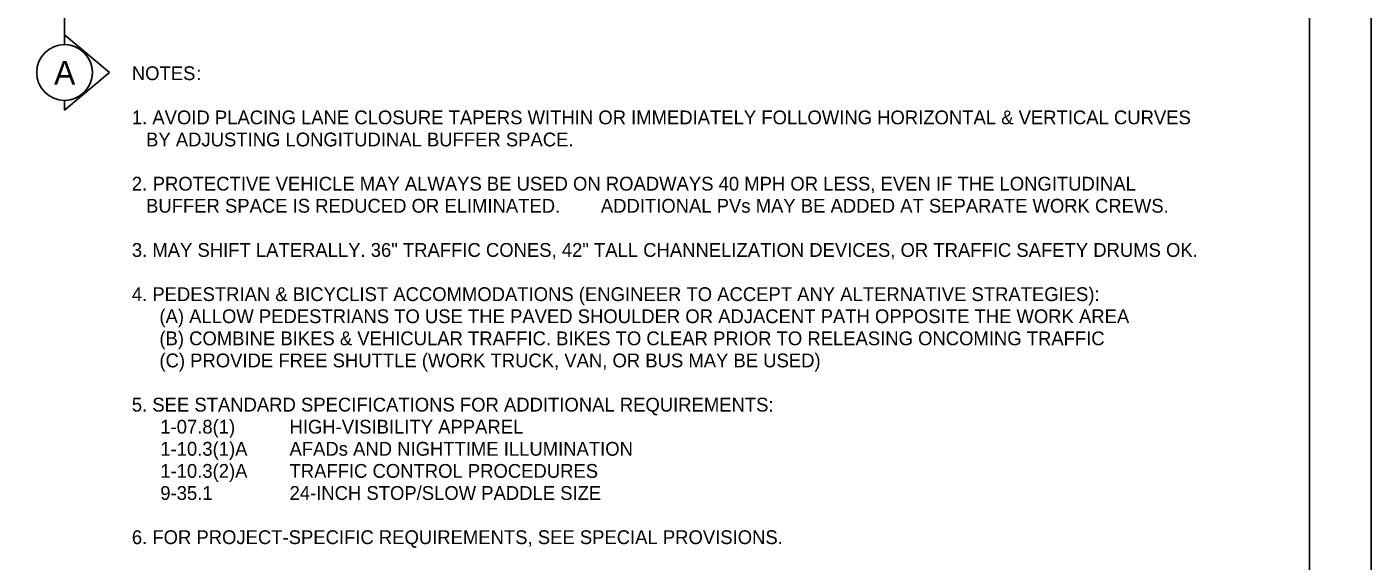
# Model space of a CAD drawing. Extents: x 99999.1 to 100095.7, y 99995 to 100010.7.
# Drawn here: x 100009.24 to 100016.06, y 100002.9 to 100005.61 of the extents above; entities that cross this region are included whole.
import ezdxf

# ---------------------------------------------------------------- set-up
doc = ezdxf.new("R2010")
doc.units = 0
for name, color, linetype in [('SH_GI_GeneralNotesBodyText', 7, 'Continuous'), ('SH_GI_PlotLimits', 7, 'Continuous'), ('SH_GI_SheetBorder', 7, 'Continuous'), ('SH_TI_WZSectionCut', 7, 'Continuous')]:
    doc.layers.add(name, color=color, linetype=linetype)

msp = doc.modelspace()

# ---------------------------------------------------------------- linework, layer by layer
at = {"layer": 'SH_GI_PlotLimits'}
msp.add_lwpolyline([(99999.0625, 99999.6875), (100016.0625, 99999.6875), (100016.0625, 100010.6875), (99999.0625, 100010.6875)], close=True, dxfattribs=at)
at = {"layer": 'SH_GI_SheetBorder'}
msp.add_line((100015.75, 100010.375), (100015.75, 100000), dxfattribs=at)
at = {"layer": 'SH_TI_WZSectionCut'}
for p, q in [((100009.4338, 100007.7022), (100009.4338, 100005.5723)), ((100009.4337, 100005.5723), (100009.4337, 100005.5224)), ((100009.6619, 100005.3812), (100009.4337, 100005.5723)), ((100009.4337, 100005.1901), (100009.6619, 100005.3812)), ((100009.4337, 100005.24), (100009.4337, 100005.1901))]:
    msp.add_line(p, q, dxfattribs=at)
msp.add_circle((100009.4338, 100005.3812), 0.1412, dxfattribs=at)
msp.add_arc((100009.4338, 100005.3812), 0.1412, 269.99779, 90.00221, dxfattribs=at)

# ---------------------------------------------------------------- texts
at = {"layer": 'SH_GI_GeneralNotesBodyText'}
for s, p in [('NOTES', (100009.7751, 100005.3426)), (':', (100010.1026, 100005.3426)), ('1. AVOID PLACING LANE CLOSURE TAPERS WITHIN OR IMMEDIATELY FOLLOWING HORIZONTAL & VERTICAL CURVES ', (100009.7751, 100005.1186)), ('BY ADJUSTING LONGITUDINAL BUFFER SPACE.', (100009.8473, 100005.0066)), ('2. ', (100009.7751, 100004.7826)), ('PROTECTIVE VEHICLE MAY ALWAYS BE USED ON ROADWAYS 40 MPH OR LESS, EVEN IF THE LONGITUDINAL ', (100009.8808, 100004.7826)), ('BUFFER SPACE IS REDUCED OR ELIMINATED.', (100009.8473, 100004.6706)), ('  ADDITIONAL PVs MAY BE ADDED AT SEPARATE WORK CREWS.', (100012.1026, 100004.6706)), ('3. MAY SHIFT LATERALLY. 36" TRAFFIC CONES, 42" TALL CHANNELIZATION DEVICES, OR TRAFFIC SAFETY DRUMS OK.', (100009.7751, 100004.4466)), ('4. PEDESTRIAN & BICYCLIST ACCOMMODATIONS (ENGINEER TO ACCEPT ANY ALTERNATIVE STRATEGIES):', (100009.7751, 100004.2226)), ('(A) ALLOW PEDESTRIANS TO USE THE PAVED SHOULDER OR ADJACENT PATH OPPOSITE THE WORK AREA', (100009.9151, 100004.1106)), ('(B) COMBINE BIKES & VEHICULAR TRAFFIC. BIKES TO CLEAR PRIOR TO RELEASING ONCOMING TRAFFIC', (100009.9151, 100003.9986)), ('(C) PROVIDE FREE SHUTTLE (WORK TRUCK, VAN, OR BUS MAY BE USED)', (100009.9151, 100003.8866)), ('5. SEE STANDARD SPECIFICATIONS FOR ADDITIONAL REQUIREMENTS:', (100009.7751, 100003.6626)), ('1-07.8(1) ', (100009.9195, 100003.5506)), ('HIGH-VISIBILITY APPAREL', (100010.5751, 100003.5506)), ('1-10.3(1)A ', (100009.9195, 100003.4386)), ('AFADs AND NIGHTTIME ILLUMINATION', (100010.5751, 100003.4386)), ('1-10.3(2)A', (100009.9195, 100003.3266)), ('TRAFFIC CONTROL PROCEDURES', (100010.5751, 100003.3266)), ('9-35.1', (100009.9195, 100003.2146)), ('24-INCH STOP/SLOW PADDLE SIZE', (100010.5751, 100003.2146)), ('6. FOR PROJECT-SPECIFIC REQUIREMENTS, SEE SPECIAL PROVISIONS.', (100009.7751, 100002.9906))]:
    msp.add_text(s, height=0.07, rotation=360, dxfattribs=at).set_placement(p)
at = {"layer": 'SH_TI_WZSectionCut'}
msp.add_text('A', height=0.12, rotation=0.00995, dxfattribs=at).set_placement((100009.3808, 100005.3203))

doc.saveas('drawing.dxf')
